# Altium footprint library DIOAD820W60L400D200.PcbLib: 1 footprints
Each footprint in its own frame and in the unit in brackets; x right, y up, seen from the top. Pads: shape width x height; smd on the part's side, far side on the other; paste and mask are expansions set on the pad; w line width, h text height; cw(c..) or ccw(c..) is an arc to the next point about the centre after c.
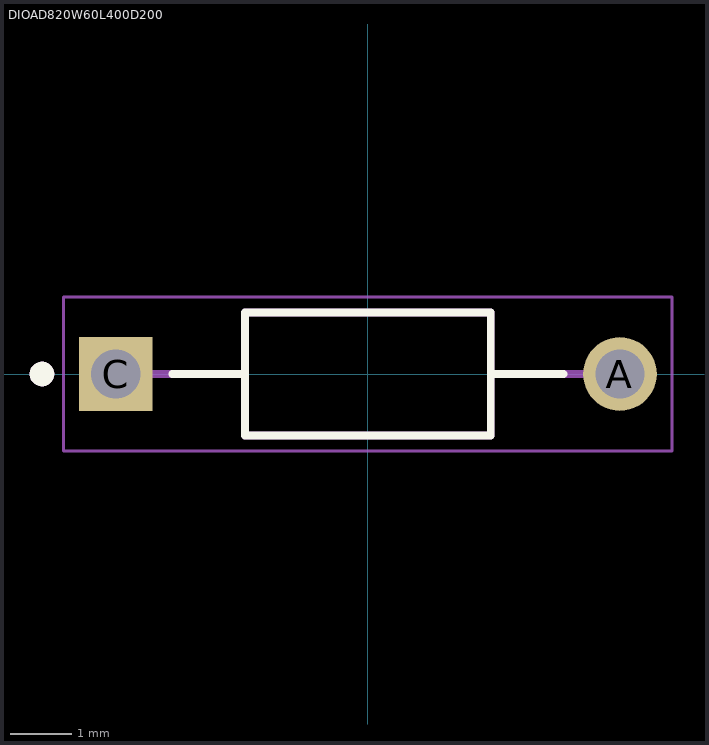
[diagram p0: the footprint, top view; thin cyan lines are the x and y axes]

## DIOAD820W60L400D200 [mm]
pads (2):
  round 1.2 hole 0.8: A(4.1,0)
  rect 1.2x1.2 hole 0.8: C(-4.1,0)
Top Overlay:
  circle w0.2: c-5.3,0 r0.1
  lines w0.127: -3.18,0 -2,0 ; 3.18,0 2,0 ; -2,0 -2,1 2,1 2,0 ; -2,0 -2,-1 2,-1 2,0
Mechanical 13:
  circle w0.2: c-5.3,0 r0.1
  lines w0.127: -3.5,0 -2,0 ; 3.5,0 2,0 ; -2,0 -2,1 2,1 2,0 ; -2,0 -2,-1 2,-1 2,0
Mechanical 15:
  lines w0.05: -4.95,-1.25 -4.95,1.25 4.95,1.25 4.95,-1.25 -4.95,-1.25
3D body "step_temp.STEP": height 1.91, standoff 0, extent -27.303,-0.955 27.303,0.955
